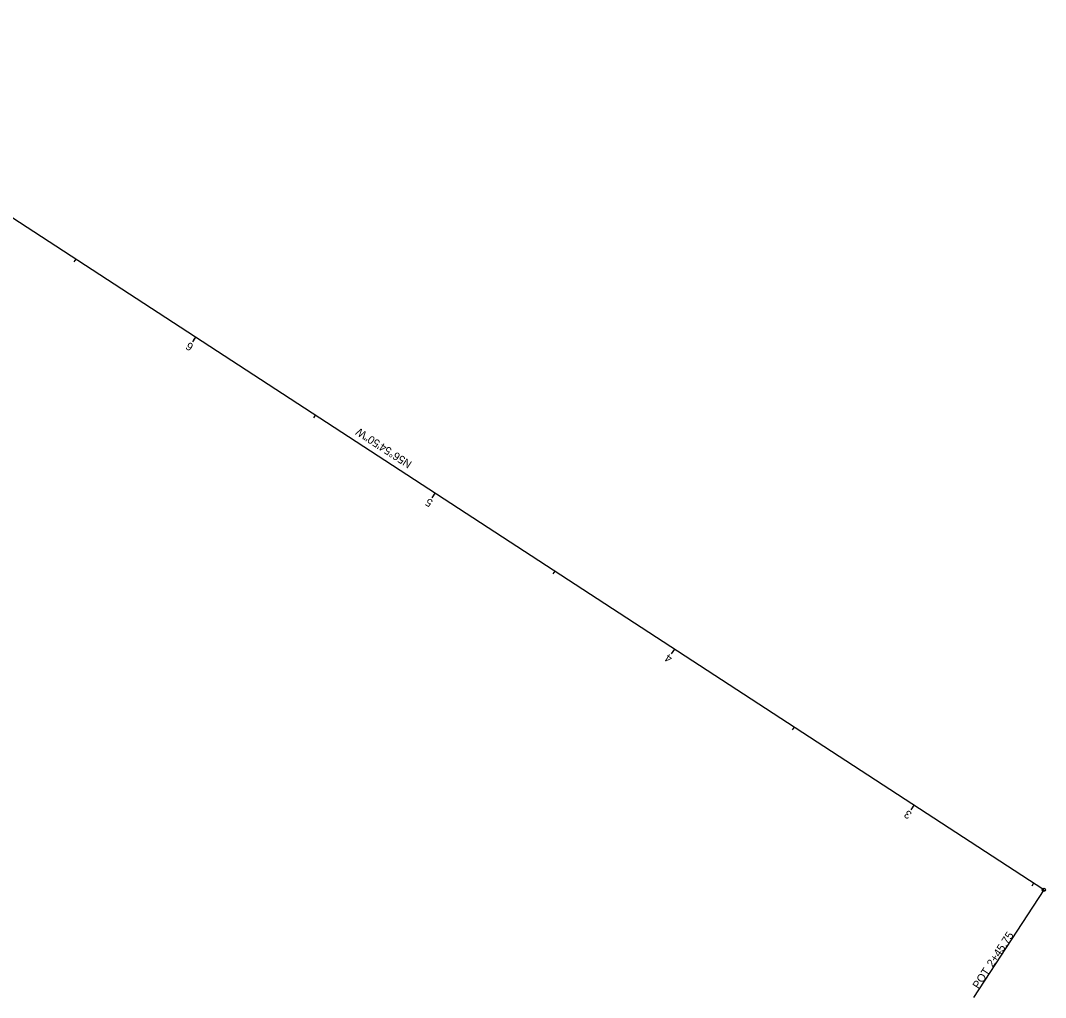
# Model space of a CAD drawing. Extents: x 2195310 to 2196150, y 661045 to 662024.
# Drawn here: x 2195791.1 to 2196149.7, y 661045.1 to 661387 of the extents above; entities that cross this region are included whole.
import ezdxf

# ---------------------------------------------------------------- set-up
doc = ezdxf.new("R2010")
doc.units = 0
for name, color, linetype in [('Default', 7, 'Continuous'), ('GE_X_Alignment', 7, 'Continuous'), ('GE_X_Alignment_1000_Stations', 7, 'Continuous'), ('GE_X_Alignment_100_Stations', 7, 'Continuous'), ('GE_X_Alignment_500_Stations', 7, 'Continuous')]:
    doc.layers.add(name, color=color, linetype=linetype)

msp = doc.modelspace()

# ---------------------------------------------------------------- linework, layer by layer
at = {"layer": 'Default'}
for centre in [(2195852.29, 661276.23), (2195915.67, 661234.93), (2195915.67, 661234.93), (2195915.67, 661234.93), (2195915.67, 661234.93), (2195915.67, 661234.93), (2195915.67, 661234.93), (2195936.08, 661221.64), (2195936.08, 661221.64), (2196019.86, 661167.05), (2196103.65, 661112.46), (2196149.1, 661082.85), (2196149.1, 661082.85), (2196149.1, 661082.85)]:
    msp.add_circle(centre, 0.0000833, dxfattribs=at)
at = {"layer": 'GE_X_Alignment'}
msp.add_line((2196149.1, 661082.85), (2195682.25, 661387.02), dxfattribs=at)
at = {"layer": 'GE_X_Alignment_1000_Stations'}
for p, q in [((2195936.08, 661221.64), (2195935.42, 661220.64)), ((2196149.1, 661082.85), (2196124.54, 661045.14))]:
    msp.add_line(p, q, dxfattribs=at)
msp.add_circle((2196149.1, 661082.85), 0.6, dxfattribs=at)
at = {"layer": 'GE_X_Alignment_100_Stations'}
for p, q in [((2195810.4, 661303.53), (2195809.74, 661302.52)), ((2195852.29, 661276.23), (2195851.2, 661274.56)), ((2195894.18, 661248.94), (2195893.53, 661247.93)), ((2195936.08, 661221.64), (2195934.99, 661219.97)), ((2195977.97, 661194.35), (2195977.31, 661193.34)), ((2196019.86, 661167.05), (2196018.77, 661165.38)), ((2196061.75, 661139.76), (2196061.1, 661138.75)), ((2196103.65, 661112.46), (2196102.56, 661110.79)), ((2196145.54, 661085.17), (2196144.88, 661084.16)), ((2196149.1, 661082.85), (2196124.54, 661045.14))]:
    msp.add_line(p, q, dxfattribs=at)
msp.add_circle((2196149.1, 661082.85), 0.6, dxfattribs=at)
at = {"layer": 'GE_X_Alignment_500_Stations'}
for p, q in [((2195852.29, 661276.23), (2195851.64, 661275.23)), ((2195936.08, 661221.64), (2195934.99, 661219.97)), ((2196019.86, 661167.05), (2196019.21, 661166.05)), ((2196103.65, 661112.46), (2196102.99, 661111.46)), ((2196149.1, 661082.85), (2196124.54, 661045.14))]:
    msp.add_line(p, q, dxfattribs=at)
msp.add_circle((2196149.1, 661082.85), 0.6, dxfattribs=at)

# ---------------------------------------------------------------- texts
at = {"layer": 'GE_X_Alignment_1000_Stations'}
for s, rotation, p in [('N56°54\'50"W', 146.914, (2195928.24, 661232.48)), ('2+45.75', 56.914, (2196131.27, 661055.57)), ('POT', 56.914, (2196126.29, 661047.92))]:
    msp.add_text(s, height=2.8, rotation=rotation, dxfattribs=at).set_placement(p)
at = {"layer": 'GE_X_Alignment_100_Stations'}
for s, rotation, p in [('6', 146.914, (2195851.83, 661273.49)), ('N56°54\'50"W', 146.914, (2195928.24, 661232.48)), ('5', 146.914, (2195935.62, 661218.9)), ('4', 146.914, (2196019.39, 661164.38)), ('3', 146.914, (2196103.17, 661109.73)), ('2+45.75', 56.914, (2196131.27, 661055.57)), ('POT', 56.914, (2196126.29, 661047.92))]:
    msp.add_text(s, height=2.8, rotation=rotation, dxfattribs=at).set_placement(p)
at = {"layer": 'GE_X_Alignment_500_Stations'}
for s, rotation, p in [('N56°54\'50"W', 146.914, (2195928.24, 661232.48)), ('5', 146.914, (2195935.62, 661218.9)), ('2+45.75', 56.914, (2196131.27, 661055.57)), ('POT', 56.914, (2196126.29, 661047.92))]:
    msp.add_text(s, height=2.8, rotation=rotation, dxfattribs=at).set_placement(p)

doc.saveas('drawing.dxf')
